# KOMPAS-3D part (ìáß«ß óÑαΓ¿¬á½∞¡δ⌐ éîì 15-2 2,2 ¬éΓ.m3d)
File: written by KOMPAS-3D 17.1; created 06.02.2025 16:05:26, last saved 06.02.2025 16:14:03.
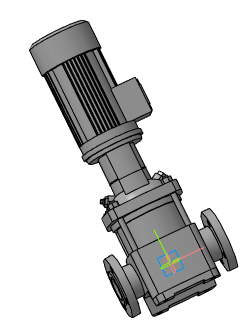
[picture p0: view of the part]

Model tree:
1. Операция без истории:2  (labels: Насос вертикальный ВМН 15-2 2,2 кВт)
